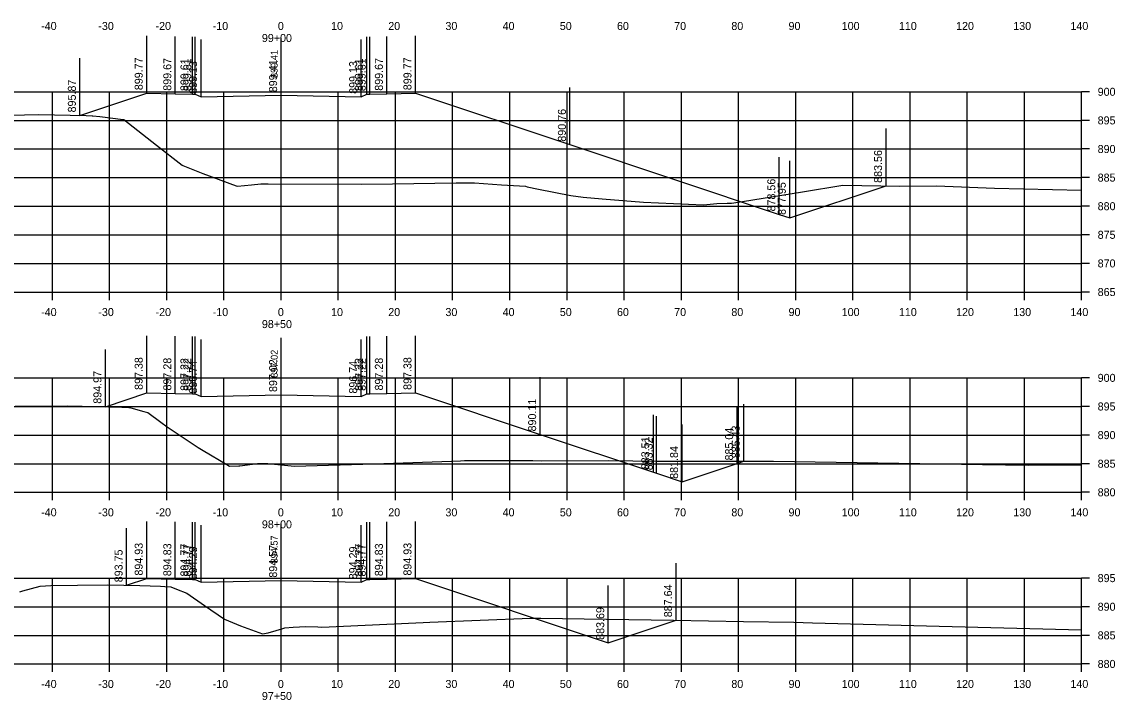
# Model space of a CAD drawing. Extents: x 1098669 to 1198896, y 698679 to 704410.
# Drawn here: x 1111950.2 to 1112141.4, y 701574.7 to 701693.2 of the extents above; entities that cross this region are included whole.
import ezdxf

# ---------------------------------------------------------------- set-up
doc = ezdxf.new("R2010")
doc.units = 0
for name, color, linetype in [('59', 7, 'Continuous'), ('Proposed Surface', 7, 'Continuous'), ('R_Axis', 7, 'Continuous'), ('R_Axis Annot', 7, 'Continuous'), ('R_Fin Surface', 7, 'Continuous'), ('R_Grid', 7, 'Continuous'), ('R_Xsect Elev', 7, 'Continuous')]:
    doc.layers.add(name, color=color, linetype=linetype)

msp = doc.modelspace()

# ---------------------------------------------------------------- linework, layer by layer
at = {"layer": 'Proposed Surface'}
for points in [[(1111945.64, 701676.97), (1111950.67, 701677.03), (1111953.1, 701677.07), (1111961.46, 701676.87), (1111962.49, 701676.85), (1111962.64, 701676.83), (1111963.85, 701676.72), (1111967.91, 701676.2), (1111968.02, 701676.18), (1111973.74, 701671.71), (1111978.26, 701668.19), (1111978.36, 701668.14), (1111981.88, 701666.72), (1111987.7, 701664.61), (1111987.93, 701664.53), (1111990.35, 701664.77), (1111991.98, 701664.92), (1111993.3, 701664.93), (1112009.53, 701664.9), (1112015.03, 701664.93), (1112026.17, 701665.1), (1112027.88, 701665.11), (1112029.37, 701665.12), (1112034.07, 701664.76), (1112038.3, 701664.51), (1112038.59, 701664.42), (1112040.57, 701664), (1112046.19, 701662.89), (1112048.35, 701662.61), (1112051.7, 701662.3), (1112058.92, 701661.73), (1112069.4, 701661.28), (1112071.76, 701661.51), (1112073.54, 701661.56), (1112074.14, 701661.54), (1112074.3, 701661.55), (1112076.22, 701661.86), (1112086.73, 701663.55), (1112093.78, 701664.68), (1112103.78, 701664.56), (1112110.14, 701664.6), (1112120.28, 701664.19), (1112135.55, 701663.82)], [(1111949.05, 701626.08), (1111951.49, 701626.1), (1111958.26, 701626.16), (1111960.75, 701626.1), (1111967.72, 701625.92), (1111968.95, 701625.83), (1111969.26, 701625.8), (1111971.55, 701625.15), (1111972.24, 701625), (1111974.5, 701623.3), (1111975.61, 701622.46), (1111981.07, 701618.87), (1111981.95, 701618.31), (1111986.05, 701615.9), (1111986.53, 701615.57), (1111988.16, 701615.65), (1111988.34, 701615.66), (1111991.4, 701616.07), (1111993.22, 701616.08), (1111997.87, 701615.6), (1112011.82, 701616.03), (1112013.52, 701616.08), (1112025.33, 701616.47), (1112026.92, 701616.53), (1112027.63, 701616.56), (1112039.57, 701616.58), (1112041.13, 701616.55), (1112052.79, 701616.56), (1112061.31, 701616.47), (1112071.46, 701616.45), (1112081.64, 701616.46), (1112118.21, 701615.91), (1112126.22, 701615.75), (1112135.55, 701615.82)], [(1111949.87, 701593.63), (1111950.39, 701593.78), (1111953.43, 701594.62), (1111954.36, 701594.68), (1111955.29, 701594.74), (1111959.93, 701594.79), (1111965.26, 701594.86), (1111970.87, 701594.72), (1111974.45, 701594.62), (1111975.2, 701594.57), (1111976.27, 701594.49), (1111977.28, 701594.09), (1111979.09, 701593.4), (1111982.18, 701591.26), (1111985.66, 701588.88), (1111988.44, 701587.69), (1111992.28, 701586.3), (1111993.29, 701586.48), (1111994.71, 701586.85), (1111995.69, 701587.19), (1111996.23, 701587.37), (1111997.67, 701587.46), (1111999.87, 701587.6), (1112001.95, 701587.52), (1112002.68, 701587.48), (1112014.06, 701588.01), (1112020.37, 701588.27), (1112021.59, 701588.32), (1112039.16, 701589.03), (1112040.99, 701589.03), (1112048.57, 701588.94), (1112064.2, 701588.68), (1112076.43, 701588.47), (1112085.22, 701588.31), (1112088.46, 701588.19), (1112110.66, 701587.65), (1112135.55, 701587.02)]]:
    msp.add_lwpolyline(points, dxfattribs=at)
at = {"layer": 'R_Axis'}
for p, q in [((1112135.55, 701646.03), (1112135.55, 701681.03)), ((1112136.95, 701681.03), (1112135.55, 701681.03)), ((1112136.95, 701676.03), (1112135.55, 701676.03)), ((1112136.95, 701671.03), (1112135.55, 701671.03)), ((1112136.95, 701666.03), (1112135.55, 701666.03)), ((1112136.95, 701661.03), (1112135.55, 701661.03)), ((1112136.95, 701656.03), (1112135.55, 701656.03)), ((1112136.95, 701651.03), (1112135.55, 701651.03)), ((1111855.55, 701646.03), (1112135.55, 701646.03)), ((1111955.55, 701644.63), (1111955.55, 701646.03)), ((1111965.55, 701644.63), (1111965.55, 701646.03)), ((1111975.55, 701644.63), (1111975.55, 701646.03)), ((1111985.55, 701644.63), (1111985.55, 701646.03)), ((1111995.55, 701644.63), (1111995.55, 701646.03)), ((1112005.55, 701644.63), (1112005.55, 701646.03)), ((1112015.55, 701644.63), (1112015.55, 701646.03)), ((1112025.55, 701644.63), (1112025.55, 701646.03)), ((1112035.55, 701644.63), (1112035.55, 701646.03)), ((1112045.55, 701644.63), (1112045.55, 701646.03)), ((1112055.55, 701644.63), (1112055.55, 701646.03)), ((1112065.55, 701644.63), (1112065.55, 701646.03)), ((1112075.55, 701644.63), (1112075.55, 701646.03)), ((1112085.55, 701644.63), (1112085.55, 701646.03)), ((1112095.55, 701644.63), (1112095.55, 701646.03)), ((1112105.55, 701644.63), (1112105.55, 701646.03)), ((1112115.55, 701644.63), (1112115.55, 701646.03)), ((1112125.55, 701644.63), (1112125.55, 701646.03)), ((1112135.55, 701644.63), (1112135.55, 701646.03)), ((1112136.95, 701646.03), (1112135.55, 701646.03)), ((1112135.55, 701611.03), (1112135.55, 701631.03)), ((1112136.95, 701631.03), (1112135.55, 701631.03)), ((1112136.95, 701626.03), (1112135.55, 701626.03)), ((1112136.95, 701621.03), (1112135.55, 701621.03)), ((1112136.95, 701616.03), (1112135.55, 701616.03)), ((1111855.55, 701611.03), (1112135.55, 701611.03)), ((1111955.55, 701609.63), (1111955.55, 701611.03)), ((1111965.55, 701609.63), (1111965.55, 701611.03)), ((1111975.55, 701609.63), (1111975.55, 701611.03)), ((1111985.55, 701609.63), (1111985.55, 701611.03)), ((1111995.55, 701609.63), (1111995.55, 701611.03)), ((1112005.55, 701609.63), (1112005.55, 701611.03)), ((1112015.55, 701609.63), (1112015.55, 701611.03)), ((1112025.55, 701609.63), (1112025.55, 701611.03)), ((1112035.55, 701609.63), (1112035.55, 701611.03)), ((1112045.55, 701609.63), (1112045.55, 701611.03)), ((1112055.55, 701609.63), (1112055.55, 701611.03)), ((1112065.55, 701609.63), (1112065.55, 701611.03)), ((1112075.55, 701609.63), (1112075.55, 701611.03)), ((1112085.55, 701609.63), (1112085.55, 701611.03)), ((1112095.55, 701609.63), (1112095.55, 701611.03)), ((1112105.55, 701609.63), (1112105.55, 701611.03)), ((1112115.55, 701609.63), (1112115.55, 701611.03)), ((1112125.55, 701609.63), (1112125.55, 701611.03)), ((1112135.55, 701609.63), (1112135.55, 701611.03)), ((1112136.95, 701611.03), (1112135.55, 701611.03)), ((1112135.55, 701581.03), (1112135.55, 701596.03)), ((1112136.95, 701596.03), (1112135.55, 701596.03)), ((1112136.95, 701591.03), (1112135.55, 701591.03)), ((1112136.95, 701586.03), (1112135.55, 701586.03)), ((1111855.55, 701581.03), (1112135.55, 701581.03)), ((1111955.55, 701579.63), (1111955.55, 701581.03)), ((1111965.55, 701579.63), (1111965.55, 701581.03)), ((1111975.55, 701579.63), (1111975.55, 701581.03)), ((1111985.55, 701579.63), (1111985.55, 701581.03)), ((1111995.55, 701579.63), (1111995.55, 701581.03)), ((1112005.55, 701579.63), (1112005.55, 701581.03)), ((1112015.55, 701579.63), (1112015.55, 701581.03)), ((1112025.55, 701579.63), (1112025.55, 701581.03)), ((1112035.55, 701579.63), (1112035.55, 701581.03)), ((1112045.55, 701579.63), (1112045.55, 701581.03)), ((1112055.55, 701579.63), (1112055.55, 701581.03)), ((1112065.55, 701579.63), (1112065.55, 701581.03)), ((1112075.55, 701579.63), (1112075.55, 701581.03)), ((1112085.55, 701579.63), (1112085.55, 701581.03)), ((1112095.55, 701579.63), (1112095.55, 701581.03)), ((1112105.55, 701579.63), (1112105.55, 701581.03)), ((1112115.55, 701579.63), (1112115.55, 701581.03)), ((1112125.55, 701579.63), (1112125.55, 701581.03)), ((1112135.55, 701579.63), (1112135.55, 701581.03)), ((1112136.95, 701581.03), (1112135.55, 701581.03))]:
    msp.add_line(p, q, dxfattribs=at)
at = {"layer": 'R_Fin Surface'}
for points in [[(1111960.36, 701676.9), (1111972.05, 701680.79), (1111977.05, 701680.69), (1111980.05, 701680.63), (1111980.55, 701680.63), (1111981.55, 701680.15), (1111995.55, 701680.43), (1112009.55, 701680.15), (1112010.55, 701680.63), (1112011.05, 701680.63), (1112014.05, 701680.69), (1112019.05, 701680.79), (1112046.06, 701671.79), (1112082.68, 701659.59), (1112084.51, 701658.98), (1112101.34, 701664.59)], [(1111964.83, 701625.99), (1111972.05, 701628.4), (1111977.05, 701628.3), (1111980.05, 701628.24), (1111980.55, 701628.24), (1111981.55, 701627.76), (1111995.55, 701628.04), (1112009.55, 701627.76), (1112010.55, 701628.24), (1112011.05, 701628.24), (1112014.05, 701628.3), (1112019.05, 701628.4), (1112040.85, 701621.14), (1112060.65, 701614.54), (1112061.22, 701614.35), (1112065.67, 701612.86), (1112075.3, 701616.07), (1112076.45, 701616.46)], [(1111968.53, 701594.78), (1111972.05, 701595.95), (1111977.05, 701595.85), (1111980.05, 701595.79), (1111980.55, 701595.79), (1111981.55, 701595.31), (1111995.55, 701595.59), (1112009.55, 701595.31), (1112010.55, 701595.79), (1112011.05, 701595.79), (1112014.05, 701595.85), (1112019.05, 701595.95), (1112052.76, 701584.72), (1112064.62, 701588.67)]]:
    msp.add_lwpolyline(points, dxfattribs=at)
at = {"layer": 'R_Grid'}
for p, q in [((1111855.55, 701681.03), (1112135.55, 701681.03)), ((1111955.55, 701646.03), (1111955.55, 701681.03)), ((1111965.55, 701646.03), (1111965.55, 701681.03)), ((1111975.55, 701646.03), (1111975.55, 701681.03)), ((1111985.55, 701646.03), (1111985.55, 701681.03)), ((1111995.55, 701646.03), (1111995.55, 701681.03)), ((1112005.55, 701646.03), (1112005.55, 701681.03)), ((1112015.55, 701646.03), (1112015.55, 701681.03)), ((1112025.55, 701646.03), (1112025.55, 701681.03)), ((1112035.55, 701646.03), (1112035.55, 701681.03)), ((1112045.55, 701646.03), (1112045.55, 701681.03)), ((1112055.55, 701646.03), (1112055.55, 701681.03)), ((1112065.55, 701646.03), (1112065.55, 701681.03)), ((1112075.55, 701646.03), (1112075.55, 701681.03)), ((1112085.55, 701646.03), (1112085.55, 701681.03)), ((1112095.55, 701646.03), (1112095.55, 701681.03)), ((1112105.55, 701646.03), (1112105.55, 701681.03)), ((1112115.55, 701646.03), (1112115.55, 701681.03)), ((1112125.55, 701646.03), (1112125.55, 701681.03)), ((1112135.55, 701646.03), (1112135.55, 701681.03)), ((1111855.55, 701676.03), (1112135.55, 701676.03)), ((1111855.55, 701671.03), (1112135.55, 701671.03)), ((1111855.55, 701666.03), (1112135.55, 701666.03)), ((1111855.55, 701661.03), (1112135.55, 701661.03)), ((1111855.55, 701656.03), (1112135.55, 701656.03)), ((1111855.55, 701651.03), (1112135.55, 701651.03)), ((1111855.55, 701646.03), (1112135.55, 701646.03)), ((1111855.55, 701631.03), (1112135.55, 701631.03)), ((1111955.55, 701611.03), (1111955.55, 701631.03)), ((1111965.55, 701611.03), (1111965.55, 701631.03)), ((1111975.55, 701611.03), (1111975.55, 701631.03)), ((1111985.55, 701611.03), (1111985.55, 701631.03)), ((1111995.55, 701611.03), (1111995.55, 701631.03)), ((1112005.55, 701611.03), (1112005.55, 701631.03)), ((1112015.55, 701611.03), (1112015.55, 701631.03)), ((1112025.55, 701611.03), (1112025.55, 701631.03)), ((1112035.55, 701611.03), (1112035.55, 701631.03)), ((1112045.55, 701611.03), (1112045.55, 701631.03)), ((1112055.55, 701611.03), (1112055.55, 701631.03)), ((1112065.55, 701611.03), (1112065.55, 701631.03)), ((1112075.55, 701611.03), (1112075.55, 701631.03)), ((1112085.55, 701611.03), (1112085.55, 701631.03)), ((1112095.55, 701611.03), (1112095.55, 701631.03)), ((1112105.55, 701611.03), (1112105.55, 701631.03)), ((1112115.55, 701611.03), (1112115.55, 701631.03)), ((1112125.55, 701611.03), (1112125.55, 701631.03)), ((1112135.55, 701611.03), (1112135.55, 701631.03)), ((1111855.55, 701626.03), (1112135.55, 701626.03)), ((1111855.55, 701621.03), (1112135.55, 701621.03)), ((1111855.55, 701616.03), (1112135.55, 701616.03)), ((1111855.55, 701611.03), (1112135.55, 701611.03)), ((1111855.55, 701596.03), (1112135.55, 701596.03)), ((1111955.55, 701581.03), (1111955.55, 701596.03)), ((1111965.55, 701581.03), (1111965.55, 701596.03)), ((1111975.55, 701581.03), (1111975.55, 701596.03)), ((1111985.55, 701581.03), (1111985.55, 701596.03)), ((1111995.55, 701581.03), (1111995.55, 701596.03)), ((1112005.55, 701581.03), (1112005.55, 701596.03)), ((1112015.55, 701581.03), (1112015.55, 701596.03)), ((1112025.55, 701581.03), (1112025.55, 701596.03)), ((1112035.55, 701581.03), (1112035.55, 701596.03)), ((1112045.55, 701581.03), (1112045.55, 701596.03)), ((1112055.55, 701581.03), (1112055.55, 701596.03)), ((1112065.55, 701581.03), (1112065.55, 701596.03)), ((1112075.55, 701581.03), (1112075.55, 701596.03)), ((1112085.55, 701581.03), (1112085.55, 701596.03)), ((1112095.55, 701581.03), (1112095.55, 701596.03)), ((1112105.55, 701581.03), (1112105.55, 701596.03)), ((1112115.55, 701581.03), (1112115.55, 701596.03)), ((1112125.55, 701581.03), (1112125.55, 701596.03)), ((1112135.55, 701581.03), (1112135.55, 701596.03)), ((1111855.55, 701591.03), (1112135.55, 701591.03)), ((1111855.55, 701586.03), (1112135.55, 701586.03)), ((1111855.55, 701581.03), (1112135.55, 701581.03))]:
    msp.add_line(p, q, dxfattribs=at)
at = {"layer": 'R_Xsect Elev'}
for p, q in [((1111972.05, 701680.79), (1111972.05, 701690.79)), ((1111977.05, 701680.69), (1111977.05, 701690.69)), ((1111980.05, 701680.63), (1111980.05, 701690.63)), ((1111980.55, 701680.63), (1111980.55, 701690.63)), ((1112010.55, 701680.63), (1112010.55, 701690.63)), ((1112011.05, 701680.63), (1112011.05, 701690.63)), ((1112014.05, 701680.69), (1112014.05, 701690.69)), ((1112019.05, 701680.79), (1112019.05, 701690.79)), ((1111981.55, 701680.15), (1111981.55, 701690.15)), ((1111995.55, 701680.43), (1111995.55, 701690.43)), ((1111995.55, 701680.43), (1111995.55, 701690.43)), ((1112009.55, 701680.15), (1112009.55, 701690.15)), ((1111960.36, 701676.9), (1111960.36, 701686.9)), ((1112046.06, 701671.79), (1112046.06, 701681.79)), ((1112101.34, 701664.59), (1112101.34, 701674.59)), ((1112082.68, 701659.59), (1112082.68, 701669.59)), ((1112084.51, 701658.98), (1112084.51, 701668.98)), ((1111972.05, 701628.4), (1111972.05, 701638.4)), ((1111977.05, 701628.3), (1111977.05, 701638.3)), ((1111980.05, 701628.24), (1111980.05, 701638.24)), ((1111980.55, 701628.24), (1111980.55, 701638.24)), ((1111981.55, 701627.76), (1111981.55, 701637.76)), ((1111995.55, 701628.04), (1111995.55, 701638.04)), ((1111995.55, 701628.04), (1111995.55, 701638.04)), ((1112009.55, 701627.76), (1112009.55, 701637.76)), ((1112010.55, 701628.24), (1112010.55, 701638.24)), ((1112011.05, 701628.24), (1112011.05, 701638.24)), ((1112014.05, 701628.3), (1112014.05, 701638.3)), ((1112019.05, 701628.4), (1112019.05, 701638.4)), ((1111964.83, 701625.99), (1111964.83, 701635.99)), ((1112040.85, 701621.14), (1112040.85, 701631.14)), ((1112075.3, 701616.07), (1112075.3, 701626.07)), ((1112076.45, 701616.46), (1112076.45, 701626.46)), ((1112060.65, 701614.54), (1112060.65, 701624.54)), ((1112061.22, 701614.35), (1112061.22, 701624.35)), ((1112065.67, 701612.86), (1112065.67, 701622.86)), ((1111968.53, 701594.78), (1111968.53, 701604.78)), ((1111972.05, 701595.95), (1111972.05, 701605.95)), ((1111977.05, 701595.85), (1111977.05, 701605.85)), ((1111980.05, 701595.79), (1111980.05, 701605.79)), ((1111980.55, 701595.79), (1111980.55, 701605.79)), ((1111981.55, 701595.31), (1111981.55, 701605.31)), ((1111995.55, 701595.59), (1111995.55, 701605.59)), ((1111995.55, 701595.59), (1111995.55, 701605.59)), ((1112009.55, 701595.31), (1112009.55, 701605.31)), ((1112010.55, 701595.79), (1112010.55, 701605.79)), ((1112011.05, 701595.79), (1112011.05, 701605.79)), ((1112014.05, 701595.85), (1112014.05, 701605.85)), ((1112019.05, 701595.95), (1112019.05, 701605.95)), ((1112064.62, 701588.67), (1112064.62, 701598.67)), ((1112052.76, 701584.72), (1112052.76, 701594.72))]:
    msp.add_line(p, q, dxfattribs=at)

# ---------------------------------------------------------------- texts
at = {"layer": '59'}
for s, p in [(' 899.77', (1111971.35, 701680.79)), (' 899.67', (1111976.35, 701680.69)), (' 899.61', (1111979.35, 701680.63)), (' 899.61', (1111979.85, 701680.63)), (' 899.61', (1112009.85, 701680.63)), (' 899.61', (1112010.35, 701680.63)), (' 899.67', (1112013.35, 701680.69)), (' 899.77', (1112018.35, 701680.79)), (' 899.13', (1111980.85, 701680.15)), (' 899.41', (1111994.85, 701680.43)), (' 899.13', (1112008.85, 701680.15)), (' 895.87', (1111959.66, 701676.9)), (' 890.76', (1112045.36, 701671.79)), (' 883.56', (1112100.64, 701664.59)), (' 878.56', (1112081.98, 701659.59)), (' 877.95', (1112083.81, 701658.98)), (' 897.38', (1111971.35, 701628.4)), (' 897.28', (1111976.35, 701628.3)), (' 897.22', (1111979.35, 701628.24)), (' 897.22', (1111979.85, 701628.24)), (' 896.74', (1111980.85, 701627.76)), (' 897.02', (1111994.85, 701628.04)), (' 896.74', (1112008.85, 701627.76)), (' 897.22', (1112009.85, 701628.24)), (' 897.22', (1112010.35, 701628.24)), (' 897.28', (1112013.35, 701628.3)), (' 897.38', (1112018.35, 701628.4)), (' 894.97', (1111964.13, 701625.99)), (' 890.11', (1112040.15, 701621.14)), (' 885.04', (1112074.6, 701616.07)), (' 885.43', (1112075.75, 701616.46)), (' 883.51', (1112059.95, 701614.54)), (' 883.32', (1112060.52, 701614.35)), (' 881.84', (1112064.97, 701612.86)), (' 893.75', (1111967.83, 701594.78)), (' 894.93', (1111971.35, 701595.95)), (' 894.83', (1111976.35, 701595.85)), (' 894.77', (1111979.35, 701595.79)), (' 894.77', (1111979.85, 701595.79)), (' 894.29', (1111980.85, 701595.31)), (' 894.57', (1111994.85, 701595.59)), (' 894.29', (1112008.85, 701595.31)), (' 894.77', (1112009.85, 701595.79)), (' 894.77', (1112010.35, 701595.79)), (' 894.83', (1112013.35, 701595.85)), (' 894.93', (1112018.35, 701595.95)), (' 887.64', (1112063.92, 701588.67)), (' 883.69', (1112052.06, 701584.72))]:
    msp.add_text(s, height=1.4, rotation=90, dxfattribs=at).set_placement(p)
at = {"layer": 'R_Axis Annot'}
for s, p in [('-40', (1111953.59, 701691.83)), ('-30', (1111963.59, 701691.83)), ('-20', (1111973.59, 701691.83)), ('-10', (1111983.59, 701691.83)), ('0', (1111994.99, 701691.83)), ('10', (1112004.29, 701691.83)), ('20', (1112014.29, 701691.83)), ('30', (1112024.29, 701691.83)), ('40', (1112034.29, 701691.83)), ('50', (1112044.29, 701691.83)), ('60', (1112054.29, 701691.83)), ('70', (1112064.29, 701691.83)), ('80', (1112074.29, 701691.83)), ('90', (1112084.29, 701691.83)), ('100', (1112093.59, 701691.83)), ('110', (1112103.59, 701691.83)), ('120', (1112113.59, 701691.83)), ('130', (1112123.59, 701691.83)), ('140', (1112133.59, 701691.83)), ('99+00', (1111992.19, 701689.73)), ('900', (1112138.35, 701680.33)), ('895', (1112138.35, 701675.33)), ('890', (1112138.35, 701670.33)), ('885', (1112138.35, 701665.33)), ('880', (1112138.35, 701660.33)), ('875', (1112138.35, 701655.33)), ('870', (1112138.35, 701650.33)), ('865', (1112138.35, 701645.33)), ('-40', (1111953.59, 701641.83)), ('-30', (1111963.59, 701641.83)), ('-20', (1111973.59, 701641.83)), ('-10', (1111983.59, 701641.83)), ('0', (1111994.99, 701641.83)), ('10', (1112004.29, 701641.83)), ('20', (1112014.29, 701641.83)), ('30', (1112024.29, 701641.83)), ('40', (1112034.29, 701641.83)), ('50', (1112044.29, 701641.83)), ('60', (1112054.29, 701641.83)), ('70', (1112064.29, 701641.83)), ('80', (1112074.29, 701641.83)), ('90', (1112084.29, 701641.83)), ('100', (1112093.59, 701641.83)), ('110', (1112103.59, 701641.83)), ('120', (1112113.59, 701641.83)), ('130', (1112123.59, 701641.83)), ('140', (1112133.59, 701641.83)), ('98+50', (1111992.19, 701639.73)), ('900', (1112138.35, 701630.33)), ('895', (1112138.35, 701625.33)), ('890', (1112138.35, 701620.33)), ('885', (1112138.35, 701615.33)), ('880', (1112138.35, 701610.33)), ('-40', (1111953.59, 701606.83)), ('-30', (1111963.59, 701606.83)), ('-20', (1111973.59, 701606.83)), ('-10', (1111983.59, 701606.83)), ('0', (1111994.99, 701606.83)), ('10', (1112004.29, 701606.83)), ('20', (1112014.29, 701606.83)), ('30', (1112024.29, 701606.83)), ('40', (1112034.29, 701606.83)), ('50', (1112044.29, 701606.83)), ('60', (1112054.29, 701606.83)), ('70', (1112064.29, 701606.83)), ('80', (1112074.29, 701606.83)), ('90', (1112084.29, 701606.83)), ('100', (1112093.59, 701606.83)), ('110', (1112103.59, 701606.83)), ('120', (1112113.59, 701606.83)), ('130', (1112123.59, 701606.83)), ('140', (1112133.59, 701606.83)), ('98+00', (1111992.19, 701604.73)), ('895', (1112138.35, 701595.33)), ('890', (1112138.35, 701590.33)), ('885', (1112138.35, 701585.33)), ('880', (1112138.35, 701580.33)), ('-40', (1111953.59, 701576.83)), ('-30', (1111963.59, 701576.83)), ('-20', (1111973.59, 701576.83)), ('-10', (1111983.59, 701576.83)), ('0', (1111994.99, 701576.83)), ('10', (1112004.29, 701576.83)), ('20', (1112014.29, 701576.83)), ('30', (1112024.29, 701576.83)), ('40', (1112034.29, 701576.83)), ('50', (1112044.29, 701576.83)), ('60', (1112054.29, 701576.83)), ('70', (1112064.29, 701576.83)), ('80', (1112074.29, 701576.83)), ('90', (1112084.29, 701576.83)), ('100', (1112093.59, 701576.83)), ('110', (1112103.59, 701576.83)), ('120', (1112113.59, 701576.83)), ('130', (1112123.59, 701576.83)), ('140', (1112133.59, 701576.83)), ('97+50', (1111992.19, 701574.73))]:
    msp.add_text(s, height=1.4, dxfattribs=at).set_placement(p)
at = {"layer": 'R_Xsect Elev'}
for s, p in [('899.41', (1111994.95, 701683.43)), ('897.02', (1111994.95, 701631.04)), ('894.57', (1111994.95, 701598.59))]:
    msp.add_text(s, height=1.2, rotation=90, dxfattribs=at).set_placement(p)

doc.saveas('drawing.dxf')
